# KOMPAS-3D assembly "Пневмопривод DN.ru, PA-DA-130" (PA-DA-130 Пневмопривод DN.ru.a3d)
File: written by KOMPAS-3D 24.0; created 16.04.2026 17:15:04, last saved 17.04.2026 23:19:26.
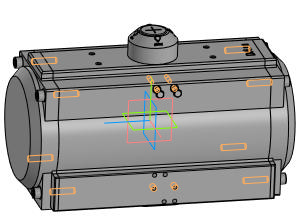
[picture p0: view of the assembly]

Document properties: Автор: DN.ru; Полное имя файла: C:\Работа\PA-DA-х Пневмопривод DN.ru\130\исходные материалы\PA-DA-130 Пневмопривод DN.ru.a3d

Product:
- Component [detail]: Пневмопривод DN.ru  | designation PA-DA-130  | qty 1  | pos. 1  | Масса: 8.9; Раздел спецификации: Прочие изделия; Примечание: D290-00297; Автор: DN.ru; source file: PA-DA-130 Пневмопривод DN.ru.m3d
- Component [standard]: (unnamed)  | qty 8  | pos. 2  | Масса: 0.02082; Раздел спецификации: Стандартные изделия; Рассекать на разрезах: no; additional columns: М8-6gx40; Винт; ГОСТ 11738-84
- Component [standard]: Болт М5-6gx50 ГОСТ 7805-70  | qty 2  | Масса: 0.008999; Раздел спецификации: Стандартные изделия; Рассекать на разрезах: no
- Component [standard]: Гайка М5-6H ГОСТ 5915-70  | qty 2  | Масса: 0.00144; Раздел спецификации: Стандартные изделия; Рассекать на разрезах: no
- Part/product: Пневмопривод DN.ru  | designation PA-DA-130
    Масса: 8.9
    Раздел спецификации: Прочие изделия
    Примечание: D290-00297

Expressions: D290-00297
Referenced files in C:\Работа\PA-DA-х Пневмопривод DN.ru\130\исходные материалы\: PA-DA-130 Пневмопривод DN.ru.m3d
Referenced files in C:\Program Files\ASCON\KOMPAS-3D v24\Libs\PolynomLib\DATA\vault\Methods\Kompas\3D\: PLib_Screw_GOST_11738_1500.m3d, PLib_Bolt_1_900.m3d, PLib_Nut_OST92_900.m3d
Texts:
  PA-DA-130
  BOSimple***PART:1ff84fa3-e62c-5a6d-126f-35e3f1af4542***SHORTLOC:Root±30±20±10±80±10±GMC90[Нет;Без покрытия;Без указания материала;0,7;-;30;4]
  Крепежное изделие ГОСТ
  BOSimple***PART:53acba15-081d-1c02-6810-072b309dd366***SHORTLOC:Root±30±20±10±80±10±©{}30±©{BASE}130±30[Нет;Без покрытия;Без указания материала;50;5;8;0,8;-]
  BOSimple***PART:0338bb82-6b79-df62-da33-8b23172f1b3e***SHORTLOC:Root±30±10±20±©{}110±10±50±60[Нет;Без покрытия;Без указания материала;-;5;0,8;8]
  Программные изделия  и базы данных
  BOSimple***PART:d807d535-b71f-aebb-1123-973396afaf10***SHORTLOC:Root±30±20±10±80±10±GMC90[Нет;Без покрытия;Без указания материала;1,25;-;40;8]
  PA-DA-130 Пневмопривод DN.ru
  Деталь (1)
  Болт М5-6gx50 ГОСТ 7805-70 (1)
  hole1
  hole2
  Болт М5-6gx50 ГОСТ 7805-70 (2)
  Гайка М5-6H ГОСТ 5915-70 (1)
  bcut1
  hcut1
  cut1
  Гайка М5-6H ГОСТ 5915-70 (2)
  Деталь (2)
  Деталь (3)
  Деталь (4)
  Деталь (5)
  Деталь (6)
  Деталь (7)
  Деталь (8)
  Plane. Начало координат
